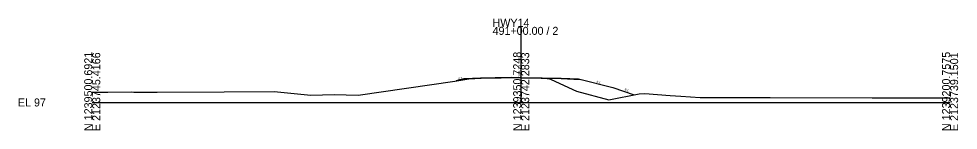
# Model space of a CAD drawing. Extents: x -26 to 303, y -10 to 11521.
# Drawn here: x -25.7 to 302.8, y 2490.3 to 2529.2 of the extents above; entities that cross this region are included whole.
import ezdxf

# ---------------------------------------------------------------- set-up
doc = ezdxf.new("R2010")
doc.units = 0
for name, color, linetype in [('XS_CELL', 7, 'Continuous'), ('XS_P_FINISHED_GRADE', 7, 'Continuous'), ('XS_P_SUBGRADE_GRANULAR', 7, 'Continuous'), ('XS_P_SUBGRADE_LEVELING', 7, 'Continuous'), ('XS_P_TX_FS_BS', 7, 'Continuous'), ('XS_X_GROUND', 7, 'Continuous'), ('XS_X_GROUND_TX', 7, 'Continuous')]:
    doc.layers.add(name, color=color, linetype=linetype)

msp = doc.modelspace()

# ---------------------------------------------------------------- linework, layer by layer
at = {"layer": 'XS_CELL'}
for p, q in [((150, 2500), (150, 2526.4)), ((0, 2500), (150, 2500)), ((150, 2500), (300, 2500))]:
    msp.add_line(p, q, dxfattribs=at)
at = {"layer": 'XS_P_FINISHED_GRADE'}
for p, q in [((130, 2508.21), (127.28, 2507.53)), ((136, 2508.45), (130, 2508.21)), ((150, 2508.73), (136, 2508.45)), ((150, 2508.73), (164, 2508.45)), ((164, 2508.45), (170, 2508.21)), ((170, 2508.21), (182, 2505.21)), ((182, 2505.21), (189.53, 2502.7))]:
    msp.add_line(p, q, dxfattribs=at)
at = {"layer": 'XS_P_SUBGRADE_GRANULAR'}
for p, q in [((136, 2508.32), (129.4, 2508.06)), ((164, 2508.32), (170.6, 2508.06))]:
    msp.add_line(p, q, dxfattribs=at)
at = {"layer": 'XS_P_SUBGRADE_LEVELING'}
for p, q in [((150, 2508.6), (136, 2508.32)), ((136, 2508.32), (136, 2508.45)), ((150, 2508.6), (164, 2508.32)), ((164, 2508.32), (164, 2508.45))]:
    msp.add_line(p, q, dxfattribs=at)
at = {"layer": 'XS_X_GROUND'}
for p, q in [((92.96, 2502.55), (126.84, 2507.46)), ((126.84, 2507.46), (131.7, 2508.2)), ((131.7, 2508.2), (132.96, 2508.35)), ((132.96, 2508.35), (135.81, 2508.54)), ((135.81, 2508.54), (140.95, 2508.66)), ((140.95, 2508.66), (146.72, 2508.8)), ((146.72, 2508.8), (150, 2508.73)), ((150, 2508.73), (154.33, 2508.64)), ((154.33, 2508.64), (157.37, 2508.58)), ((157.37, 2508.58), (159.88, 2508.24)), ((159.88, 2508.24), (160.22, 2508.09)), ((160.22, 2508.09), (160.54, 2507.95)), ((160.54, 2507.95), (169.39, 2503.96)), ((0, 2503.57), (5.5, 2503.56)), ((5.5, 2503.56), (13.84, 2503.69)), ((13.84, 2503.69), (14.57, 2503.63)), ((14.57, 2503.63), (22.66, 2503.59)), ((22.66, 2503.59), (46.15, 2503.67)), ((46.15, 2503.67), (63.58, 2503.77)), ((63.58, 2503.77), (76.48, 2502.5)), ((169.39, 2503.96), (180.65, 2500.93)), ((76.48, 2502.5), (84.62, 2502.76)), ((84.62, 2502.76), (92.96, 2502.55)), ((180.65, 2500.93), (191.32, 2503.06)), ((191.32, 2503.06), (193.25, 2503.13)), ((193.25, 2503.13), (202.1, 2502.42)), ((202.1, 2502.42), (205.8, 2502.17)), ((205.8, 2502.17), (212.55, 2501.77)), ((212.55, 2501.77), (237.12, 2501.7)), ((237.12, 2501.7), (272.8, 2501.63)), ((272.8, 2501.63), (294.48, 2501.58)), ((294.48, 2501.58), (300, 2501.58))]:
    msp.add_line(p, q, dxfattribs=at)

# ---------------------------------------------------------------- texts
at = {"layer": 'XS_CELL'}
for s, p in [('491+00.00 / 2', (140, 2523.6)), ('HWY14', (140, 2526.4)), ('EL 97', (-26, 2498.6))]:
    msp.add_text(s, height=2.8, dxfattribs=at).set_placement(p)
for s, p in [('N 1239500.6921', (0, 2490)), ('E 2123745.4166', (2.8, 2490)), ('N 1239350.7248', (150, 2490)), ('E 2123742.2833', (152.8, 2490)), ('N 1239200.7575', (300, 2490)), ('E 2123739.1501', (302.8, 2490))]:
    msp.add_text(s, height=2.8, rotation=90, dxfattribs=at).set_placement(p)
at = {"layer": 'XS_P_TX_FS_BS'}
for s, rotation, p in [('4:1', 14.0362, (128.06, 2507.83)), ('4:1', 345.9638, (176.21, 2506.88)), ('3:1', 341.5651, (186.02, 2504.24))]:
    msp.add_text(s, height=0.8, rotation=rotation, dxfattribs=at).set_placement(p)
at = {"layer": 'XS_X_GROUND_TX'}
msp.add_text('105.73', height=1, rotation=90, dxfattribs=at).set_placement((150, 2508.83))

doc.saveas('drawing.dxf')
